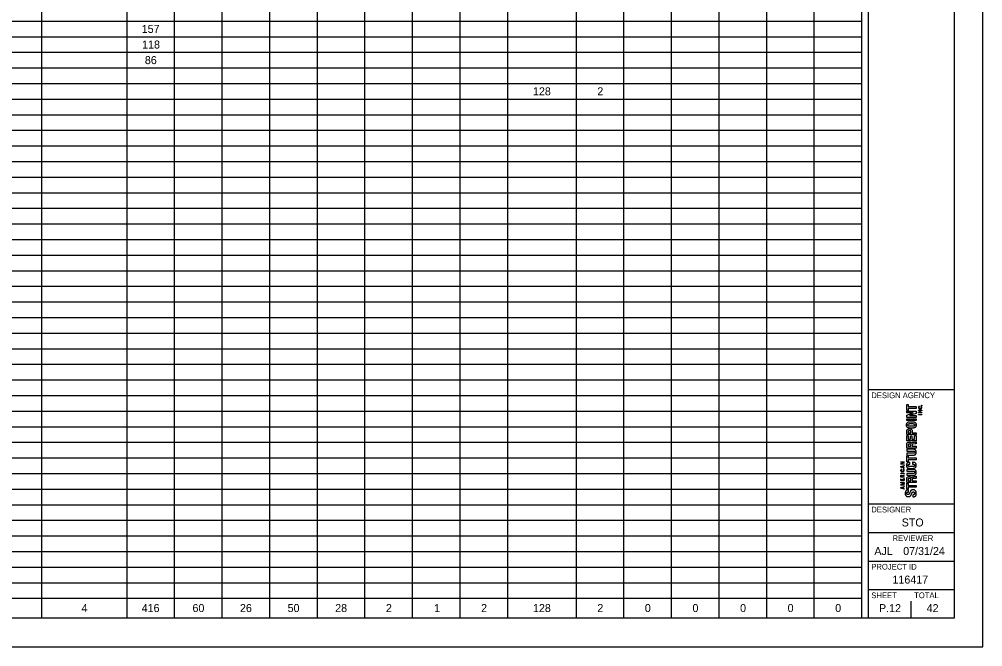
# Model space of a CAD drawing. Extents: x 0 to 34, y 0 to 22.
# Drawn here: x 17.14 to 34, y 0 to 10.98 of the extents above; entities that cross this region are included whole.
import ezdxf

# ---------------------------------------------------------------- set-up
doc = ezdxf.new("R2010")
doc.units = 0
for name, color, linetype in [('SH_Border', 7, 'Continuous'), ('SH_Cut_Line', 7, 'Continuous'), ('SH_Data', 7, 'Continuous')]:
    doc.layers.add(name, color=color, linetype=linetype)

msp = doc.modelspace()

# ---------------------------------------------------------------- linework, layer by layer
at = {"layer": 'SH_Border'}
for p, q in [((32, 0.5), (32, 21.5)), ((32, 4.5), (33.5, 4.5)), ((32, 2.5), (33.5, 2.5)), ((32, 2), (33.5, 2)), ((32, 1.5), (33.5, 1.5)), ((32, 1), (33.5, 1))]:
    msp.add_line(p, q, dxfattribs=at)
msp.add_lwpolyline([(1.5, 21.5), (33.5, 21.5), (33.5, 0.5), (1.5, 0.5)], close=True, dxfattribs=at)
at = {"layer": 'SH_Cut_Line'}
msp.add_lwpolyline([(0, 0), (34, 0), (34, 22), (0, 22)], close=True, dxfattribs=at)
at = {"layer": 'SH_Data'}
for p, q in [((17.539, 0.506), (17.539, 21.5)), ((19.027, 0.506), (19.027, 21.5)), ((19.859, 0.506), (19.859, 21.5)), ((20.692, 0.506), (20.692, 21.5)), ((21.525, 0.506), (21.525, 21.5)), ((22.357, 0.506), (22.357, 21.5)), ((23.19, 0.506), (23.19, 21.5)), ((24.022, 0.506), (24.022, 21.5)), ((24.855, 0.506), (24.855, 21.5)), ((25.688, 0.506), (25.688, 21.5)), ((26.889, 0.506), (26.889, 21.5)), ((27.722, 0.506), (27.722, 21.5)), ((28.554, 0.506), (28.554, 21.5)), ((29.387, 0.506), (29.387, 21.5)), ((30.22, 0.506), (30.22, 21.5)), ((31.052, 0.506), (31.052, 21.5)), ((31.885, 0.506), (31.885, 21.5)), ((1.5, 10.949), (31.885, 10.949)), ((1.5, 10.676), (31.885, 10.676)), ((1.5, 10.403), (31.885, 10.403)), ((1.5, 10.13), (31.885, 10.13)), ((1.5, 9.857), (31.885, 9.857)), ((1.5, 9.584), (31.885, 9.584)), ((1.5, 9.311), (31.885, 9.311)), ((1.5, 9.038), (31.885, 9.038)), ((1.5, 8.765), (31.885, 8.765)), ((1.5, 8.492), (31.885, 8.492)), ((1.5, 8.219), (31.885, 8.219)), ((1.5, 7.946), (31.885, 7.946)), ((1.5, 7.673), (31.885, 7.673)), ((1.5, 7.4), (31.885, 7.4)), ((1.5, 7.127), (31.885, 7.127)), ((1.5, 6.854), (31.885, 6.854)), ((1.5, 6.581), (31.885, 6.581)), ((1.5, 6.308), (31.885, 6.308)), ((1.5, 6.035), (31.885, 6.035)), ((1.5, 5.762), (31.885, 5.762)), ((1.5, 5.489), (31.885, 5.489)), ((1.5, 5.216), (31.885, 5.216)), ((1.5, 4.943), (31.885, 4.943)), ((1.5, 4.67), (31.885, 4.67)), ((1.5, 4.397), (31.885, 4.397)), ((1.5, 4.124), (31.885, 4.124)), ((1.5, 3.851), (31.885, 3.851)), ((1.5, 3.578), (31.885, 3.578)), ((32.75, 3.5), (32.75, 3.5)), ((32.75, 3.5), (32.75, 3.5)), ((1.5, 3.305), (31.885, 3.305)), ((1.5, 3.032), (31.885, 3.032)), ((1.5, 2.759), (31.885, 2.759)), ((1.5, 2.486), (31.885, 2.486)), ((1.5, 2.213), (31.885, 2.213)), ((1.5, 1.94), (31.885, 1.94)), ((1.5, 1.667), (31.885, 1.667)), ((1.5, 1.394), (31.885, 1.394)), ((1.5, 1.121), (31.885, 1.121)), ((1.5, 0.848), (31.885, 0.848)), ((32.375, 0.675), (32.375, 0.675)), ((32.75, 0.5), (32.75, 0.8)), ((1.5, 0.506), (31.885, 0.506))]:
    msp.add_line(p, q, dxfattribs=at)
for points in [[(32.67, 4.239), (32.697, 4.239), (32.697, 4.204), (32.833, 4.204), (32.833, 4.171), (32.697, 4.171), (32.697, 4.135), (32.67, 4.135), (32.67, 4.239)], [(32.935, 4.218), (32.927, 4.218), (32.927, 4.225), (32.935, 4.225), (32.935, 4.218)], [(32.67, 4.051), (32.781, 4.091), (32.781, 4.092), (32.67, 4.092), (32.67, 4.122), (32.833, 4.122), (32.833, 4.084), (32.719, 4.044), (32.719, 4.044), (32.833, 4.044), (32.833, 4.013), (32.67, 4.013), (32.67, 4.051)], [(32.875, 4.096), (32.875, 4.105), (32.925, 4.134), (32.925, 4.134), (32.875, 4.134), (32.875, 4.139), (32.935, 4.139), (32.935, 4.134), (32.88, 4.102), (32.88, 4.101), (32.935, 4.101), (32.935, 4.096), (32.875, 4.096)], [(32.875, 4.061), (32.875, 4.067), (32.935, 4.067), (32.935, 4.061), (32.875, 4.061)], [(32.833, 3.957), (32.67, 3.957), (32.67, 3.99), (32.833, 3.99), (32.833, 3.957)], [(32.833, 3.712), (32.67, 3.712), (32.67, 3.769)], [(32.694, 3.744), (32.743, 3.744), (32.743, 3.759)], [(32.694, 3.758), (32.694, 3.744)], [(32.768, 3.762), (32.768, 3.744), (32.833, 3.744), (32.833, 3.712)], [(32.67, 3.694), (32.697, 3.694), (32.697, 3.635), (32.735, 3.635), (32.735, 3.69), (32.762, 3.69), (32.762, 3.635), (32.806, 3.635), (32.806, 3.696), (32.833, 3.696), (32.833, 3.603), (32.67, 3.603), (32.67, 3.694)], [(32.752, 3.554), (32.752, 3.554)], [(32.816, 3.548), (32.784, 3.547)], [(32.832, 3.587), (32.833, 3.587), (32.833, 3.552)], [(32.833, 3.476), (32.67, 3.476), (32.67, 3.537)], [(32.694, 3.525), (32.694, 3.509)], [(32.694, 3.509), (32.741, 3.509), (32.741, 3.523)], [(32.764, 3.527), (32.764, 3.509), (32.833, 3.509), (32.833, 3.476)], [(32.565, 3.194), (32.565, 3.203), (32.615, 3.231), (32.615, 3.231), (32.565, 3.231), (32.565, 3.237), (32.625, 3.237), (32.625, 3.231), (32.569, 3.199), (32.569, 3.199), (32.625, 3.199), (32.625, 3.194), (32.565, 3.194)], [(32.67, 3.341), (32.697, 3.341), (32.697, 3.305), (32.833, 3.305), (32.833, 3.273), (32.697, 3.273), (32.697, 3.237), (32.67, 3.237), (32.67, 3.341)], [(32.625, 3.125), (32.565, 3.144), (32.565, 3.152), (32.625, 3.171), (32.625, 3.165), (32.605, 3.159), (32.605, 3.137), (32.625, 3.131), (32.625, 3.125)], [(32.565, 3.034), (32.565, 3.039), (32.625, 3.039), (32.625, 3.034), (32.565, 3.034)], [(32.601, 3.138), (32.601, 3.158), (32.569, 3.148), (32.569, 3.148), (32.601, 3.138)], [(32.596, 2.992), (32.625, 3.006), (32.625, 3), (32.597, 2.987), (32.597, 2.971), (32.625, 2.971), (32.625, 2.966), (32.565, 2.966), (32.565, 2.986)], [(32.625, 2.907), (32.565, 2.907), (32.565, 2.941), (32.569, 2.941), (32.569, 2.913), (32.591, 2.913), (32.591, 2.933), (32.596, 2.933), (32.596, 2.913), (32.62, 2.913), (32.62, 2.943), (32.625, 2.943), (32.625, 2.907)], [(32.625, 2.826), (32.565, 2.826), (32.565, 2.836), (32.615, 2.852), (32.615, 2.853), (32.565, 2.869), (32.565, 2.879), (32.625, 2.879), (32.625, 2.873), (32.569, 2.873), (32.569, 2.873), (32.625, 2.855), (32.625, 2.85), (32.569, 2.832), (32.569, 2.832), (32.625, 2.832), (32.625, 2.826)], [(32.569, 2.971), (32.593, 2.971), (32.593, 2.986)], [(32.569, 2.986), (32.569, 2.971)], [(32.833, 2.873), (32.67, 2.873), (32.67, 2.934)], [(32.694, 2.922), (32.694, 2.906)], [(32.694, 2.906), (32.741, 2.906), (32.741, 2.92)], [(32.752, 2.951), (32.752, 2.951)], [(32.764, 2.924), (32.764, 2.906), (32.833, 2.906), (32.833, 2.873)], [(32.816, 2.944), (32.784, 2.944)], [(32.832, 2.984), (32.833, 2.984), (32.833, 2.949)], [(32.625, 2.758), (32.565, 2.777), (32.565, 2.785), (32.625, 2.804), (32.625, 2.798), (32.605, 2.792), (32.605, 2.769), (32.625, 2.763), (32.625, 2.758)], [(32.601, 2.771), (32.601, 2.791), (32.569, 2.781), (32.569, 2.781), (32.601, 2.771)], [(32.67, 2.86), (32.697, 2.86), (32.697, 2.824), (32.833, 2.824), (32.833, 2.791), (32.697, 2.791), (32.697, 2.756), (32.67, 2.756), (32.67, 2.86)]]:
    msp.add_lwpolyline(points, dxfattribs=at)
for points in [[(32.893, 4.201), (32.889, 4.199), (32.885, 4.197), (32.883, 4.195), (32.88, 4.193), (32.879, 4.19), (32.879, 4.186), (32.879, 4.183), (32.88, 4.181), (32.881, 4.178), (32.882, 4.176), (32.884, 4.175), (32.887, 4.173), (32.889, 4.172), (32.892, 4.171), (32.895, 4.17), (32.898, 4.169), (32.902, 4.169), (32.905, 4.169), (32.909, 4.169), (32.912, 4.169), (32.915, 4.17), (32.919, 4.171), (32.921, 4.172), (32.924, 4.173), (32.926, 4.175), (32.928, 4.176), (32.929, 4.179), (32.931, 4.181), (32.931, 4.184), (32.931, 4.187), (32.931, 4.189), (32.931, 4.191), (32.93, 4.193), (32.929, 4.194), (32.928, 4.196), (32.927, 4.197), (32.926, 4.198), (32.924, 4.199), (32.922, 4.2), (32.921, 4.2), (32.919, 4.201), (32.917, 4.202), (32.917, 4.202), (32.918, 4.207), (32.918, 4.207), (32.92, 4.206), (32.923, 4.205), (32.925, 4.204), (32.927, 4.203), (32.929, 4.202), (32.931, 4.2), (32.932, 4.199), (32.934, 4.197), (32.934, 4.195), (32.935, 4.192), (32.936, 4.19), (32.936, 4.187), (32.936, 4.183), (32.935, 4.18), (32.934, 4.177), (32.932, 4.174), (32.93, 4.172), (32.927, 4.17), (32.925, 4.168), (32.921, 4.166), (32.918, 4.165), (32.914, 4.164), (32.91, 4.164), (32.905, 4.164), (32.901, 4.164), (32.896, 4.164), (32.893, 4.165), (32.889, 4.166), (32.886, 4.168), (32.883, 4.17), (32.88, 4.172), (32.878, 4.174), (32.877, 4.177), (32.875, 4.18), (32.875, 4.183), (32.875, 4.187), (32.875, 4.189), (32.875, 4.192), (32.876, 4.194), (32.877, 4.196), (32.878, 4.198), (32.88, 4.199), (32.881, 4.201), (32.883, 4.202), (32.885, 4.203), (32.887, 4.204), (32.889, 4.205), (32.892, 4.206), (32.892, 4.206), (32.893, 4.201), (32.893, 4.201)], [(32.751, 3.826), (32.739, 3.826), (32.727, 3.826), (32.717, 3.828), (32.706, 3.829), (32.697, 3.831), (32.69, 3.835), (32.682, 3.839), (32.677, 3.845), (32.672, 3.852), (32.668, 3.859), (32.666, 3.869), (32.666, 3.882), (32.666, 3.894), (32.668, 3.904), (32.672, 3.911), (32.677, 3.918), (32.682, 3.924), (32.69, 3.928), (32.697, 3.932), (32.706, 3.934), (32.717, 3.936), (32.727, 3.937), (32.739, 3.937), (32.751, 3.937), (32.758, 3.937), (32.764, 3.937), (32.771, 3.937)], [(32.751, 3.859), (32.762, 3.859), (32.771, 3.859), (32.779, 3.859), (32.787, 3.86), (32.793, 3.861), (32.798, 3.863), (32.803, 3.864), (32.806, 3.867), (32.808, 3.87), (32.81, 3.873), (32.812, 3.877), (32.812, 3.882), (32.812, 3.886), (32.81, 3.89), (32.808, 3.893), (32.806, 3.896), (32.803, 3.899), (32.798, 3.9), (32.793, 3.902), (32.787, 3.903), (32.779, 3.904), (32.771, 3.904), (32.762, 3.904), (32.751, 3.904), (32.74, 3.904), (32.731, 3.904), (32.723, 3.904), (32.716, 3.903), (32.709, 3.902), (32.704, 3.9), (32.7, 3.899), (32.696, 3.896), (32.694, 3.893), (32.692, 3.89), (32.691, 3.886), (32.691, 3.882), (32.691, 3.877), (32.692, 3.873), (32.694, 3.87), (32.696, 3.867), (32.7, 3.864), (32.704, 3.863), (32.709, 3.861), (32.716, 3.86), (32.723, 3.859), (32.731, 3.859), (32.74, 3.859), (32.751, 3.859)], [(32.771, 3.937), (32.776, 3.936), (32.781, 3.936), (32.785, 3.936), (32.796, 3.934), (32.805, 3.932), (32.812, 3.928), (32.82, 3.924), (32.825, 3.918), (32.83, 3.911), (32.834, 3.904), (32.836, 3.894), (32.836, 3.882), (32.836, 3.869), (32.834, 3.859), (32.83, 3.852), (32.825, 3.845), (32.82, 3.839), (32.812, 3.835), (32.805, 3.831), (32.796, 3.829), (32.785, 3.828), (32.775, 3.826), (32.763, 3.826), (32.751, 3.826)], [(32.67, 3.769), (32.67, 3.777), (32.671, 3.784), (32.674, 3.79), (32.677, 3.796), (32.68, 3.8), (32.685, 3.804), (32.689, 3.807), (32.695, 3.81), (32.701, 3.812), (32.706, 3.813), (32.712, 3.814), (32.719, 3.814), (32.727, 3.814), (32.734, 3.813), (32.741, 3.81), (32.747, 3.808), (32.752, 3.804), (32.756, 3.8), (32.76, 3.795), (32.763, 3.79), (32.765, 3.783), (32.767, 3.777), (32.768, 3.77), (32.768, 3.762)], [(32.743, 3.759), (32.743, 3.766), (32.741, 3.771), (32.737, 3.775), (32.733, 3.779), (32.727, 3.781), (32.719, 3.781), (32.711, 3.781), (32.705, 3.779), (32.7, 3.776), (32.696, 3.772), (32.694, 3.766), (32.694, 3.758)], [(32.67, 3.537), (32.67, 3.551), (32.673, 3.562), (32.68, 3.569), (32.687, 3.577), (32.698, 3.581), (32.712, 3.581), (32.723, 3.581), (32.732, 3.579), (32.739, 3.574), (32.745, 3.57), (32.75, 3.563), (32.752, 3.554)], [(32.741, 3.523), (32.741, 3.531), (32.739, 3.537), (32.735, 3.542), (32.732, 3.546), (32.725, 3.548), (32.717, 3.548), (32.702, 3.548), (32.694, 3.54), (32.694, 3.525)], [(32.752, 3.554), (32.753, 3.559), (32.755, 3.564), (32.757, 3.567), (32.759, 3.571), (32.762, 3.573), (32.766, 3.575), (32.769, 3.577), (32.774, 3.578), (32.78, 3.579), (32.786, 3.58), (32.794, 3.58), (32.802, 3.58), (32.811, 3.58), (32.818, 3.581), (32.822, 3.582), (32.827, 3.582), (32.83, 3.584), (32.832, 3.587)], [(32.784, 3.547), (32.778, 3.546), (32.773, 3.545), (32.769, 3.542), (32.766, 3.539), (32.764, 3.534), (32.764, 3.527)], [(32.833, 3.552), (32.831, 3.55), (32.828, 3.549), (32.825, 3.549), (32.822, 3.548), (32.819, 3.548), (32.816, 3.548)], [(32.67, 3.385), (32.67, 3.385), (32.783, 3.385), (32.783, 3.385), (32.787, 3.385), (32.791, 3.385), (32.795, 3.386), (32.798, 3.387), (32.801, 3.388), (32.803, 3.389), (32.806, 3.39), (32.808, 3.392), (32.809, 3.395), (32.811, 3.397), (32.812, 3.401), (32.812, 3.404), (32.812, 3.408), (32.811, 3.411), (32.809, 3.414), (32.808, 3.417), (32.806, 3.418), (32.803, 3.42), (32.801, 3.421), (32.798, 3.422), (32.795, 3.423), (32.791, 3.423), (32.787, 3.424), (32.783, 3.424), (32.783, 3.424), (32.67, 3.424), (32.67, 3.424), (32.67, 3.424), (32.67, 3.457), (32.67, 3.457), (32.67, 3.457), (32.783, 3.457), (32.783, 3.457), (32.794, 3.457), (32.802, 3.455), (32.809, 3.452), (32.816, 3.449), (32.821, 3.445), (32.825, 3.441), (32.829, 3.436), (32.832, 3.43), (32.834, 3.424), (32.835, 3.418), (32.836, 3.411), (32.836, 3.404), (32.836, 3.398), (32.835, 3.391), (32.834, 3.385), (32.833, 3.379), (32.83, 3.373), (32.826, 3.368), (32.822, 3.363), (32.817, 3.36), (32.81, 3.357), (32.803, 3.354), (32.794, 3.352), (32.783, 3.352), (32.783, 3.352), (32.67, 3.352), (32.67, 3.352), (32.67, 3.352), (32.67, 3.385), (32.67, 3.385)], [(32.725, 3.193), (32.713, 3.193), (32.704, 3.192), (32.699, 3.189), (32.693, 3.186), (32.691, 3.181), (32.691, 3.174), (32.691, 3.17), (32.692, 3.166), (32.694, 3.163), (32.696, 3.161), (32.7, 3.159), (32.705, 3.157), (32.71, 3.156), (32.716, 3.155), (32.724, 3.154), (32.732, 3.153), (32.742, 3.153), (32.753, 3.153), (32.766, 3.153), (32.776, 3.153), (32.783, 3.154), (32.791, 3.155), (32.797, 3.156), (32.801, 3.158), (32.805, 3.16), (32.808, 3.162), (32.809, 3.165), (32.811, 3.168), (32.812, 3.171), (32.812, 3.174), (32.812, 3.177), (32.811, 3.18), (32.81, 3.182), (32.809, 3.185), (32.807, 3.187), (32.804, 3.189), (32.801, 3.191), (32.797, 3.192), (32.792, 3.193), (32.786, 3.194), (32.779, 3.195), (32.77, 3.195), (32.77, 3.195), (32.77, 3.228), (32.77, 3.228), (32.779, 3.228), (32.787, 3.227), (32.795, 3.226), (32.803, 3.224), (32.81, 3.222), (32.816, 3.218), (32.822, 3.214), (32.827, 3.209), (32.831, 3.202), (32.834, 3.196), (32.836, 3.187), (32.836, 3.176), (32.836, 3.163), (32.834, 3.154), (32.83, 3.146), (32.825, 3.139), (32.82, 3.133), (32.812, 3.129), (32.805, 3.126), (32.796, 3.123), (32.785, 3.122), (32.775, 3.121), (32.763, 3.12), (32.751, 3.12), (32.739, 3.12), (32.727, 3.121), (32.717, 3.122), (32.706, 3.123), (32.697, 3.126), (32.69, 3.129), (32.682, 3.133), (32.677, 3.139), (32.672, 3.146), (32.668, 3.154), (32.666, 3.163), (32.666, 3.176), (32.666, 3.188), (32.668, 3.197), (32.672, 3.204), (32.676, 3.21), (32.681, 3.215), (32.687, 3.219), (32.692, 3.222), (32.699, 3.224), (32.706, 3.225), (32.712, 3.226), (32.719, 3.226), (32.725, 3.226), (32.725, 3.226), (32.725, 3.193), (32.725, 3.193)], [(32.582, 3.101), (32.578, 3.1), (32.575, 3.098), (32.572, 3.095), (32.57, 3.093), (32.569, 3.09), (32.569, 3.086), (32.569, 3.083), (32.569, 3.081), (32.571, 3.079), (32.572, 3.077), (32.574, 3.075), (32.576, 3.074), (32.579, 3.072), (32.581, 3.071), (32.585, 3.07), (32.588, 3.07), (32.591, 3.069), (32.595, 3.069), (32.598, 3.069), (32.602, 3.07), (32.605, 3.07), (32.608, 3.071), (32.611, 3.072), (32.613, 3.074), (32.616, 3.075), (32.618, 3.077), (32.619, 3.079), (32.62, 3.081), (32.621, 3.084), (32.621, 3.087), (32.621, 3.089), (32.62, 3.091), (32.62, 3.093), (32.619, 3.095), (32.618, 3.096), (32.617, 3.097), (32.615, 3.098), (32.614, 3.099), (32.612, 3.1), (32.61, 3.101), (32.608, 3.102), (32.606, 3.102), (32.606, 3.102), (32.607, 3.107), (32.607, 3.107), (32.61, 3.107), (32.612, 3.106), (32.615, 3.105), (32.617, 3.104), (32.619, 3.102), (32.62, 3.101), (32.622, 3.099), (32.623, 3.097), (32.624, 3.095), (32.625, 3.093), (32.625, 3.09), (32.625, 3.087), (32.625, 3.083), (32.625, 3.08), (32.623, 3.077), (32.622, 3.074), (32.62, 3.072), (32.617, 3.07), (32.614, 3.068), (32.611, 3.067), (32.607, 3.066), (32.604, 3.065), (32.599, 3.064), (32.595, 3.064), (32.59, 3.064), (32.586, 3.065), (32.582, 3.066), (32.579, 3.067), (32.575, 3.068), (32.573, 3.07), (32.57, 3.072), (32.568, 3.074), (32.566, 3.077), (32.565, 3.08), (32.564, 3.083), (32.564, 3.087), (32.564, 3.09), (32.565, 3.092), (32.566, 3.094), (32.566, 3.096), (32.568, 3.098), (32.569, 3.099), (32.571, 3.101), (32.572, 3.102), (32.575, 3.103), (32.577, 3.104), (32.579, 3.105), (32.581, 3.106), (32.581, 3.106), (32.582, 3.101), (32.582, 3.101)], [(32.67, 3.032), (32.67, 3.032), (32.783, 3.032), (32.783, 3.032), (32.787, 3.032), (32.791, 3.033), (32.795, 3.033), (32.798, 3.034), (32.801, 3.035), (32.803, 3.036), (32.806, 3.038), (32.808, 3.04), (32.809, 3.042), (32.811, 3.045), (32.812, 3.048), (32.812, 3.052), (32.812, 3.056), (32.811, 3.059), (32.809, 3.061), (32.808, 3.064), (32.806, 3.066), (32.803, 3.067), (32.801, 3.069), (32.798, 3.07), (32.795, 3.07), (32.791, 3.071), (32.787, 3.071), (32.783, 3.071), (32.783, 3.071), (32.67, 3.071), (32.67, 3.071), (32.67, 3.071), (32.67, 3.104), (32.67, 3.104), (32.67, 3.104), (32.783, 3.104), (32.783, 3.104), (32.794, 3.104), (32.802, 3.102), (32.809, 3.1), (32.816, 3.097), (32.821, 3.093), (32.825, 3.088), (32.829, 3.083), (32.832, 3.077), (32.834, 3.071), (32.835, 3.065), (32.836, 3.058), (32.836, 3.052), (32.836, 3.045), (32.835, 3.039), (32.834, 3.032), (32.833, 3.026), (32.83, 3.021), (32.826, 3.016), (32.822, 3.011), (32.817, 3.007), (32.81, 3.004), (32.803, 3.001), (32.794, 3), (32.783, 3), (32.783, 3), (32.67, 3), (32.67, 3), (32.67, 3), (32.67, 3.032), (32.67, 3.032)], [(32.565, 2.986), (32.565, 2.992), (32.566, 2.996), (32.569, 2.999), (32.572, 3.003), (32.576, 3.004), (32.581, 3.004), (32.585, 3.004), (32.588, 3.003), (32.591, 3.001), (32.593, 2.999), (32.595, 2.996), (32.596, 2.992)], [(32.593, 2.986), (32.593, 2.99), (32.592, 2.993), (32.59, 2.995), (32.588, 2.997), (32.585, 2.999), (32.581, 2.999), (32.577, 2.999), (32.575, 2.998), (32.573, 2.995), (32.57, 2.993), (32.569, 2.99), (32.569, 2.986)], [(32.67, 2.934), (32.67, 2.948), (32.673, 2.958), (32.68, 2.966), (32.687, 2.974), (32.698, 2.978), (32.712, 2.978), (32.723, 2.978), (32.732, 2.975), (32.739, 2.971), (32.745, 2.967), (32.75, 2.96), (32.752, 2.951)], [(32.741, 2.92), (32.741, 2.928), (32.739, 2.934), (32.735, 2.938), (32.732, 2.943), (32.725, 2.945), (32.717, 2.945), (32.702, 2.945), (32.694, 2.937), (32.694, 2.922)], [(32.752, 2.951), (32.753, 2.956), (32.755, 2.961), (32.757, 2.964), (32.759, 2.967), (32.762, 2.97), (32.766, 2.972), (32.769, 2.974), (32.774, 2.975), (32.78, 2.976), (32.786, 2.976), (32.794, 2.977), (32.802, 2.977), (32.811, 2.977), (32.818, 2.978), (32.822, 2.978), (32.827, 2.979), (32.83, 2.981), (32.832, 2.984)], [(32.784, 2.944), (32.778, 2.943), (32.773, 2.942), (32.769, 2.939), (32.766, 2.936), (32.764, 2.931), (32.764, 2.924)], [(32.833, 2.949), (32.831, 2.947), (32.828, 2.946), (32.825, 2.945), (32.822, 2.945), (32.819, 2.945), (32.816, 2.944)], [(32.775, 2.661), (32.775, 2.661), (32.781, 2.661), (32.781, 2.661), (32.785, 2.661), (32.789, 2.662), (32.793, 2.662), (32.796, 2.663), (32.799, 2.664), (32.801, 2.666), (32.804, 2.668), (32.806, 2.671), (32.807, 2.674), (32.809, 2.677), (32.809, 2.681), (32.809, 2.686), (32.809, 2.692), (32.807, 2.697), (32.804, 2.701), (32.8, 2.706), (32.794, 2.708), (32.786, 2.708), (32.782, 2.708), (32.779, 2.708), (32.776, 2.707), (32.773, 2.705), (32.77, 2.704), (32.767, 2.701), (32.765, 2.698), (32.763, 2.695), (32.761, 2.691), (32.759, 2.687), (32.757, 2.681), (32.755, 2.675), (32.752, 2.667), (32.749, 2.66), (32.745, 2.654), (32.742, 2.647), (32.738, 2.642), (32.734, 2.638), (32.73, 2.634), (32.725, 2.631), (32.719, 2.629), (32.713, 2.628), (32.706, 2.627), (32.699, 2.627), (32.68, 2.627), (32.667, 2.632), (32.658, 2.642), (32.649, 2.652), (32.644, 2.666), (32.644, 2.684), (32.644, 2.692), (32.645, 2.7), (32.647, 2.707), (32.649, 2.714), (32.651, 2.72), (32.656, 2.725), (32.66, 2.73), (32.665, 2.734), (32.671, 2.737), (32.677, 2.74), (32.685, 2.741), (32.694, 2.741), (32.694, 2.741), (32.699, 2.741), (32.699, 2.741), (32.699, 2.741), (32.699, 2.705), (32.699, 2.705), (32.69, 2.705), (32.683, 2.704), (32.679, 2.701), (32.674, 2.697), (32.671, 2.692), (32.671, 2.685), (32.671, 2.681), (32.672, 2.678), (32.673, 2.675), (32.675, 2.672), (32.676, 2.67), (32.678, 2.668), (32.68, 2.667), (32.682, 2.665), (32.685, 2.665), (32.688, 2.664), (32.69, 2.664), (32.693, 2.664), (32.699, 2.664), (32.704, 2.665), (32.707, 2.668), (32.711, 2.67), (32.715, 2.675), (32.718, 2.683), (32.718, 2.683), (32.731, 2.712), (32.731, 2.712), (32.734, 2.719), (32.737, 2.725), (32.74, 2.729), (32.744, 2.734), (32.747, 2.737), (32.751, 2.74), (32.755, 2.743), (32.76, 2.745), (32.764, 2.746), (32.769, 2.747), (32.774, 2.747), (32.78, 2.747), (32.799, 2.747), (32.814, 2.742), (32.823, 2.73), (32.832, 2.719), (32.837, 2.703), (32.837, 2.683), (32.837, 2.662), (32.832, 2.647), (32.823, 2.638), (32.813, 2.628), (32.8, 2.624), (32.783, 2.624), (32.783, 2.624), (32.775, 2.624), (32.775, 2.624), (32.775, 2.624), (32.775, 2.661), (32.775, 2.661)]]:
    msp.add_open_spline(points, degree=3, dxfattribs=at)

# ---------------------------------------------------------------- texts
for s, height, p in [('157', 0.14, (19.284, 10.742)), ('118', 0.14, (19.291, 10.469)), ('86', 0.14, (19.339, 10.196)), ('128', 0.14, (26.13, 9.65)), ('2', 0.14, (27.256, 9.65)), ('DESIGN AGENCY', 0.1, (32.05, 4.35)), ('DESIGNER', 0.1, (32.05, 2.35)), ('STO', 0.14, (32.582, 2.105)), ('REVIEWER', 0.1, (32.422, 1.85)), ('AJL', 0.14, (32.104, 1.605)), ('07/31/24', 0.14, (32.608, 1.605)), ('PROJECT ID', 0.1, (32.05, 1.35)), ('116417', 0.14, (32.42, 1.105)), ('SHEET', 0.1, (32.05, 0.85)), ('TOTAL', 0.1, (32.8, 0.85)), ('4', 0.14, (18.231, 0.607)), ('416', 0.14, (19.283, 0.607)), ('60', 0.14, (20.172, 0.607)), ('26', 0.14, (21.003, 0.607)), ('50', 0.14, (21.837, 0.607)), ('28', 0.14, (22.669, 0.607)), ('2', 0.14, (23.557, 0.607)), ('1', 0.14, (24.4, 0.607)), ('2', 0.14, (25.222, 0.607)), ('128', 0.14, (26.13, 0.607)), ('2', 0.14, (27.256, 0.607)), ('0', 0.14, (28.088, 0.607)), ('0', 0.14, (28.921, 0.607)), ('0', 0.14, (29.754, 0.607)), ('0', 0.14, (30.586, 0.607)), ('0', 0.14, (31.419, 0.607)), ('P.12', 0.14, (32.185, 0.605)), ('42', 0.14, (33.019, 0.605))]:
    msp.add_text(s, height=height, dxfattribs=at).set_placement(p)

doc.saveas('drawing.dxf')
